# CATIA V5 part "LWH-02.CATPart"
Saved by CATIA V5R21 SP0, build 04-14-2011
Part number: LWH-02.SLDPRT
Bounding box of the stored display mesh (mm): x -1.75 to 1.75, y -1.4 to 1.4, z 0 to 0.7
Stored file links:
  C:\Users\user\Desktop\CATIA文件\0-最新文件(2025.3月之前的慎用)\LWH-02\LWH-02.CATPart
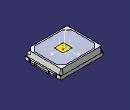
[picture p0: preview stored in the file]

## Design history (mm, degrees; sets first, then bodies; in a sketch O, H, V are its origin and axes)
AxisSystem1: origin (0, 0, 0.7), X (1, 0, 0), Y (0, 1, 0), Z (0, 0, 1)
Set1
  DatumSurface1 to DatumSurface36
  Line1: stored without definition
  Circle1: stored without definition
  Circle2: stored without definition
  Line2: stored without definition
  Circle3: stored without definition
  Line3: stored without definition
  Circle4: stored without definition
  Line4: stored without definition
  Circle5: stored without definition
  Circle6: stored without definition
  Line5: stored without definition
  Circle7: stored without definition
  Line6: stored without definition
  Circle8: stored without definition
  Line7 to Line9: stored without definition
  Circle9: stored without definition
  Line10: stored without definition
  Circle10 to Circle13: stored without definition
  Line11: stored without definition
  Circle14: stored without definition
  Line12: stored without definition
  Circle15: stored without definition
  Line13: stored without definition
  Circle16 to Circle18: stored without definition
  Line14 to Line16: stored without definition
  Circle19: stored without definition
  Line17: stored without definition
  Circle20: stored without definition
  Circle21: stored without definition
  Line18: stored without definition
  Circle22: stored without definition
  Line19: stored without definition
  Circle23: stored without definition
  Line20: stored without definition
  Circle24: stored without definition
  Circle25: stored without definition
  Line21: stored without definition
  Circle26: stored without definition
  Line22: stored without definition
  Circle27: stored without definition
  Line23 to Line25: stored without definition
  Circle28: stored without definition
  Line26: stored without definition
  Line27: stored without definition
  Circle29 to Circle31: stored without definition
  Line28: stored without definition
  Circle32: stored without definition
  Line29: stored without definition
  Circle33: stored without definition
  Line30: stored without definition
  Circle34 to Circle36: stored without definition
  Line31 to Line40: stored without definition
  DatumCurve1
  Line41 to Line65: stored without definition
  DatumSurface37 to DatumSurface52
  Circle37: stored without definition
  Circle38: stored without definition
  Line66: stored without definition
  Circle39: stored without definition
  Line67: stored without definition
  Circle40: stored without definition
  Line68: stored without definition
  Circle41 to Circle43: stored without definition
  Line69 to Line71: stored without definition
  Circle44: stored without definition
  Circle45: stored without definition
  Line72: stored without definition
  Circle46: stored without definition
  Line73: stored without definition
  Circle47: stored without definition
  Line74: stored without definition
  Circle48 to Circle50: stored without definition
  Line75 to Line77: stored without definition
  Circle51: stored without definition
  Circle52: stored without definition
  Line78 to Line91: stored without definition
  DatumSurface53 to DatumSurface88
  Line92 to Line94: stored without definition
  Circle53: stored without definition
  Line95: stored without definition
  Circle54: stored without definition
  Line96: stored without definition
  Circle55: stored without definition
  Circle56: stored without definition
  Line97: stored without definition
  Circle57: stored without definition
  Line98: stored without definition
  Circle58: stored without definition
  Line99: stored without definition
  Circle59: stored without definition
  Circle60: stored without definition
  Line100: stored without definition
  Circle61: stored without definition
  Line101: stored without definition
  Circle62 to Circle64: stored without definition
  Line102: stored without definition
  Circle65: stored without definition
  Line103: stored without definition
  Circle66: stored without definition
  Line104: stored without definition
  Circle67 to Circle69: stored without definition
  Line105 to Line107: stored without definition
  Circle70: stored without definition
  Circle71: stored without definition
  Line108 to Line110: stored without definition
  Circle72: stored without definition
  Line111: stored without definition
  Circle73: stored without definition
  Line112: stored without definition
  Circle74: stored without definition
  Circle75: stored without definition
  Line113: stored without definition
  Circle76: stored without definition
  Line114: stored without definition
  Circle77: stored without definition
  Line115: stored without definition
  Circle78: stored without definition
  Circle79: stored without definition
  Line116: stored without definition
  Circle80: stored without definition
  Line117: stored without definition
  Circle81: stored without definition
  Line118: stored without definition
  Circle82: stored without definition
  Line119: stored without definition
  Circle83: stored without definition
  Line120: stored without definition
  Circle84 to Circle86: stored without definition
  Line121 to Line123: stored without definition
  Circle87: stored without definition
  Circle88: stored without definition
  DatumCurve2
  Line124 to Line156: stored without definition
  DatumSurface89 to DatumSurface104
  Circle89: stored without definition
  Line157 to Line159: stored without definition
  Circle90 to Circle92: stored without definition
  Line160: stored without definition
  Circle93: stored without definition
  Line161: stored without definition
  Circle94: stored without definition
  Line162: stored without definition
  Circle95: stored without definition
  Circle96: stored without definition
  Line163 to Line165: stored without definition
  Circle97 to Circle99: stored without definition
  Line166: stored without definition
  Circle100: stored without definition
  Line167: stored without definition
  Circle101: stored without definition
  Line168: stored without definition
  Circle102 to Circle104: stored without definition
  Line169 to Line182: stored without definition
  DatumSurface105 to DatumSurface158
  Line183: stored without definition
  Line184: stored without definition
  Circle105: stored without definition
  Line185: stored without definition
  Circle106: stored without definition
  Line186: stored without definition
  Circle107: stored without definition
  Line187 to Line189: stored without definition
  Circle108: stored without definition
  Line190: stored without definition
  Circle109: stored without definition
  Line191: stored without definition
  Circle110: stored without definition
  Line192 to Line194: stored without definition
  Circle111: stored without definition
  Line195: stored without definition
  Circle112: stored without definition
  Line196: stored without definition
  Circle113: stored without definition
  Line197 to Line199: stored without definition
  Circle114: stored without definition
  Line200: stored without definition
  Circle115: stored without definition
  Line201: stored without definition
  Circle116: stored without definition
  Line202 to Line204: stored without definition
  Circle117: stored without definition
  Line205 to Line211: stored without definition
  Circle118: stored without definition
  Line212: stored without definition
  Line213: stored without definition
  Circle119: stored without definition
  Line214: stored without definition
  Circle120: stored without definition
  Line215: stored without definition
  Line216: stored without definition
  DatumCurve3
  Line217: stored without definition
  Line218: stored without definition
  Circle121: stored without definition
  Line219 to Line225: stored without definition
  Circle122: stored without definition
  Line226: stored without definition
  Line227: stored without definition
  Circle123: stored without definition
  Line228: stored without definition
  Circle124: stored without definition
  Line229 to Line231: stored without definition
  Circle125: stored without definition
  Line232: stored without definition
  Circle126: stored without definition
  Line233 to Line235: stored without definition
  Circle127: stored without definition
  Line236: stored without definition
  Circle128: stored without definition
  Line237: stored without definition
  Circle129: stored without definition
  Line238 to Line240: stored without definition
  Circle130: stored without definition
  Line241: stored without definition
  Circle131: stored without definition
  Line242: stored without definition
  Circle132: stored without definition
  Line243 to Line245: stored without definition
  Circle133: stored without definition
  Line246: stored without definition
  Circle134: stored without definition
  Line247: stored without definition
  Circle135: stored without definition
  Line248 to Line250: stored without definition
  Circle136: stored without definition
  Line251: stored without definition
  Circle137: stored without definition
  Line252: stored without definition
  Line253: stored without definition
  Circle138: stored without definition
  Line254: stored without definition
  Circle139: stored without definition
  Line255 to Line257: stored without definition
  Circle140: stored without definition
  Line258 to Line282: stored without definition
  Circle141: stored without definition
  Line283: stored without definition
  DatumCurve4
  Line284: stored without definition
  Line285: stored without definition
  Circle142: stored without definition
  Line286 to Line292: stored without definition
  Circle143: stored without definition
  Line293: stored without definition
  Line294: stored without definition
  Circle144: stored without definition
  Line295: stored without definition
  Line296: stored without definition
  DatumSurface159 to DatumSurface194
  Line297: stored without definition
  Circle145: stored without definition
  Line298 to Line300: stored without definition
  Circle146: stored without definition
  Line301: stored without definition
  Circle147: stored without definition
  Line302: stored without definition
  Circle148: stored without definition
  Circle149: stored without definition
  Line303: stored without definition
  Circle150: stored without definition
  Line304: stored without definition
  Circle151: stored without definition
  Line305: stored without definition
  Circle152: stored without definition
  Circle153: stored without definition
  Line306: stored without definition
  Circle154 to Circle156: stored without definition
  Line307 to Line309: stored without definition
  Circle157 to Circle159: stored without definition
  Line310: stored without definition
  Circle160: stored without definition
  Line311: stored without definition
  Circle161: stored without definition
  Line312: stored without definition
  Circle162: stored without definition
  Circle163: stored without definition
  Line313: stored without definition
  Circle164: stored without definition
  Line314 to Line316: stored without definition
  Circle165: stored without definition
  Line317: stored without definition
  Circle166: stored without definition
  Line318: stored without definition
  Circle167: stored without definition
  Circle168: stored without definition
  Line319: stored without definition
  Circle169: stored without definition
  Line320: stored without definition
  Circle170: stored without definition
  Line321: stored without definition
  Circle171: stored without definition
  Circle172: stored without definition
  Line322: stored without definition
  Circle173 to Circle175: stored without definition
  Line323 to Line325: stored without definition
  Circle176 to Circle178: stored without definition
  Line326: stored without definition
  Circle179: stored without definition
  Line327: stored without definition
  Circle180: stored without definition
  Line328 to Line362: stored without definition
  DatumSurface195 to DatumSurface230
  Line363: stored without definition
  Line364: stored without definition
  Circle181: stored without definition
  Line365: stored without definition
  Circle182: stored without definition
  Line366: stored without definition
  Circle183: stored without definition
  Circle184: stored without definition
  Line367: stored without definition
  Circle185: stored without definition
  Line368: stored without definition
  Circle186: stored without definition
  Line369: stored without definition
  Circle187: stored without definition
  Circle188: stored without definition
  Line370: stored without definition
  Circle189: stored without definition
  Line371: stored without definition
  Circle190: stored without definition
  Line372: stored without definition
  Circle191: stored without definition
  Circle192: stored without definition
  Line373 to Line375: stored without definition
  Circle193 to Circle195: stored without definition
  Line376: stored without definition
  Circle196: stored without definition
  Line377: stored without definition
  Circle197: stored without definition
  Line378: stored without definition
  Circle198: stored without definition
  Line379: stored without definition
  Circle199: stored without definition
  Line380 to Line382: stored without definition
  Circle200: stored without definition
  Line383: stored without definition
  Circle201: stored without definition
  Line384: stored without definition
  Circle202: stored without definition
  Circle203: stored without definition
  Line385: stored without definition
  Circle204: stored without definition
  Line386: stored without definition
  Circle205: stored without definition
  Line387: stored without definition
  Circle206: stored without definition
  Circle207: stored without definition
  Line388: stored without definition
  Circle208: stored without definition
  Circle209: stored without definition
  Line389 to Line391: stored without definition
  Circle210 to Circle212: stored without definition
  Line392: stored without definition
  Circle213: stored without definition
  Line393: stored without definition
  Circle214: stored without definition
  Line394: stored without definition
  Circle215: stored without definition
  Circle216: stored without definition
  Line395 to Line428: stored without definition
  DatumSurface231 to DatumSurface238
  Line429: stored without definition
  DatumCurve5
  DatumCurve6
  Line430: stored without definition
  DatumCurve7 to DatumCurve9
  Line431: stored without definition
  DatumCurve10
  Line432: stored without definition
  DatumCurve11 to DatumCurve13
  Line433: stored without definition
  DatumCurve14
  Line434: stored without definition
  Line435: stored without definition
  DatumCurve15
  Line436 to Line445: stored without definition
  DatumCurve16
  Line446: stored without definition
  DatumCurve17
  Line447 to Line462: stored without definition
  Point1 "几何中心（测试中心）": type Between, FirstPoint vertex [face of DatumSurface234], SecondPoint vertex [face of DatumSurface234], Ratio 0.5
  Point2 "虚拟坐标": (0.0886, 0.01, -0.0901), relative to Point1, in AxisSystem1
Body1 (main body)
